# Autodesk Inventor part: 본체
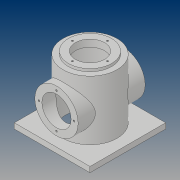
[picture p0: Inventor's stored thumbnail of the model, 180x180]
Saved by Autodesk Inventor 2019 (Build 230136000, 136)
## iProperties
Created: 2019-03
Part Number: 본체
Material: 일반
Document SubType Name: Modeling
Designer: PC312-11
Density: 1 g/cm^3
Appearance: 기본값
Author: PC312-11
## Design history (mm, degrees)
sketch "스케치1"
  geometry: L1 (50, 0)-(50, 120); L2 (27, 125)-(27, 112); L3 (27, 112)-(45, 112); L4 (45, 112)-(45, 0); L5 (45, 0)-(50, 0); L6 (0, 0)-(0, 125); L7 (50, 120)-(40, 120); L8 (40, 120)-(40, 125); L9 (40, 125)-(27, 125)
  constraints: 18 end point, 5 vertical, 4 horizontal, 2 point on line
  dimensions: "d0" = 90 diameter of L4 L6; "d1" = 100 diameter of L1 L6; "d3" = 54 diameter of L2 L6; "d4" = 112 distance between parallel lines of L5 L3; "d7" = 125 distance between parallel lines of L5 L9; "d8" = 120 distance between parallel lines of L5 L7; "d9" = 80 diameter of L8 L6
revolve "회전1" sketch "스케치1" stored, may be unused: angle "d10" = 90 deg
sketch "스케치2"
  geometry: L1 (-70, 70)-(70, 70); L2 (70, 70)-(70, -70); L3 (70, -70)-(-70, -70); L4 (-70, -70)-(-70, 70); L5 (-70, 70)-(70, -70); L6 (70, 70)-(-70, -70); C1 r 45 at (0, 0) reference; 1 further point
  constraints: 12 end point, 2 midpoint, 2 parallel, 1 horizontal, 1 perpendicular
  dimensions: "d11" = 140 distance of L2.end L3.end; "d12" = 140 distance of L1.end L2.end
extrude "돌출1" join sketch "스케치2" distance "d13" = 10; taper "d14" = 0 deg
node "작업 평면1"
sketch "스케치3"
  geometry: L1 (-70, 0)-(70, 0) reference; C1 r 40 at (0, 60); 2 further points
  constraints: 1 centre point, 1 midpoint, 1 vertical alignment
  dimensions: "d16" = 80 diameter of C1; "d17" = 60 distance from line of L1 C1.centre
extrude "돌출2" join sketch "스케치3" stored distance "d18" = 10; taper "d19" = 0 deg
sketch "스케치4" dims "d20" = 65
  geometry: C1 r 40 at (0, 0) reference; 3 further points
  constraints: 2 vertical alignment, 1 coincident, 2 other
hole "구멍1" sketch "스케치4" at (0, 32.5) diameter "d21" = 3.242; stored, may be unused: countersink angle "d25" = 90 deg, drill point angle "d27" = 118 deg; dims "d22" = 8, "d23" = 4, "d24" = 2, "d26" = 10
sketch "스케치5" dims "d31" = 65
  geometry: 3 further points
  constraints: 2 horizontal alignment, 1 coincident, 2 other
hole "구멍2" sketch "스케치5" at (-32.5, 0) diameter "d32" = 3.242; stored, may be unused: countersink angle "d36" = 90 deg, drill point angle "d38" = 118 deg; dims "d33" = 8, "d34" = 4, "d35" = 2, "d37" = 10
sketch "스케치6"
  geometry: C1 r 40 at (0, 0) reference; 2 further points
  constraints: 1 coincident
hole "구멍3" sketch "스케치6" at (0, 0) diameter "d42" = 54; stored, may be unused: countersink angle "d46" = 90 deg, drill point angle "d48" = 118 deg; dims "d43" = 8, "d44" = 4, "d45" = 2, "d47" = 10
node "솔리드1"
pattern_circular "원형 패턴1" dims angle "d29" = 360 deg
mirror "미러1"
pattern_circular "원형 패턴2" dims angle "d40" = 360 deg
other parameters: "d15" = 62
